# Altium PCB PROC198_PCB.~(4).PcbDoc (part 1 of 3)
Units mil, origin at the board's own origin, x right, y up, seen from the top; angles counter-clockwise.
Board outline 858.22 x 1632.74 mil, 4 copper layers (Top Layer, L2_GND1, L3_PWR1, Bottom Layer), stack 54.546 mil thick; 116 components, 64 nets, 355 pads, 1018 vias.
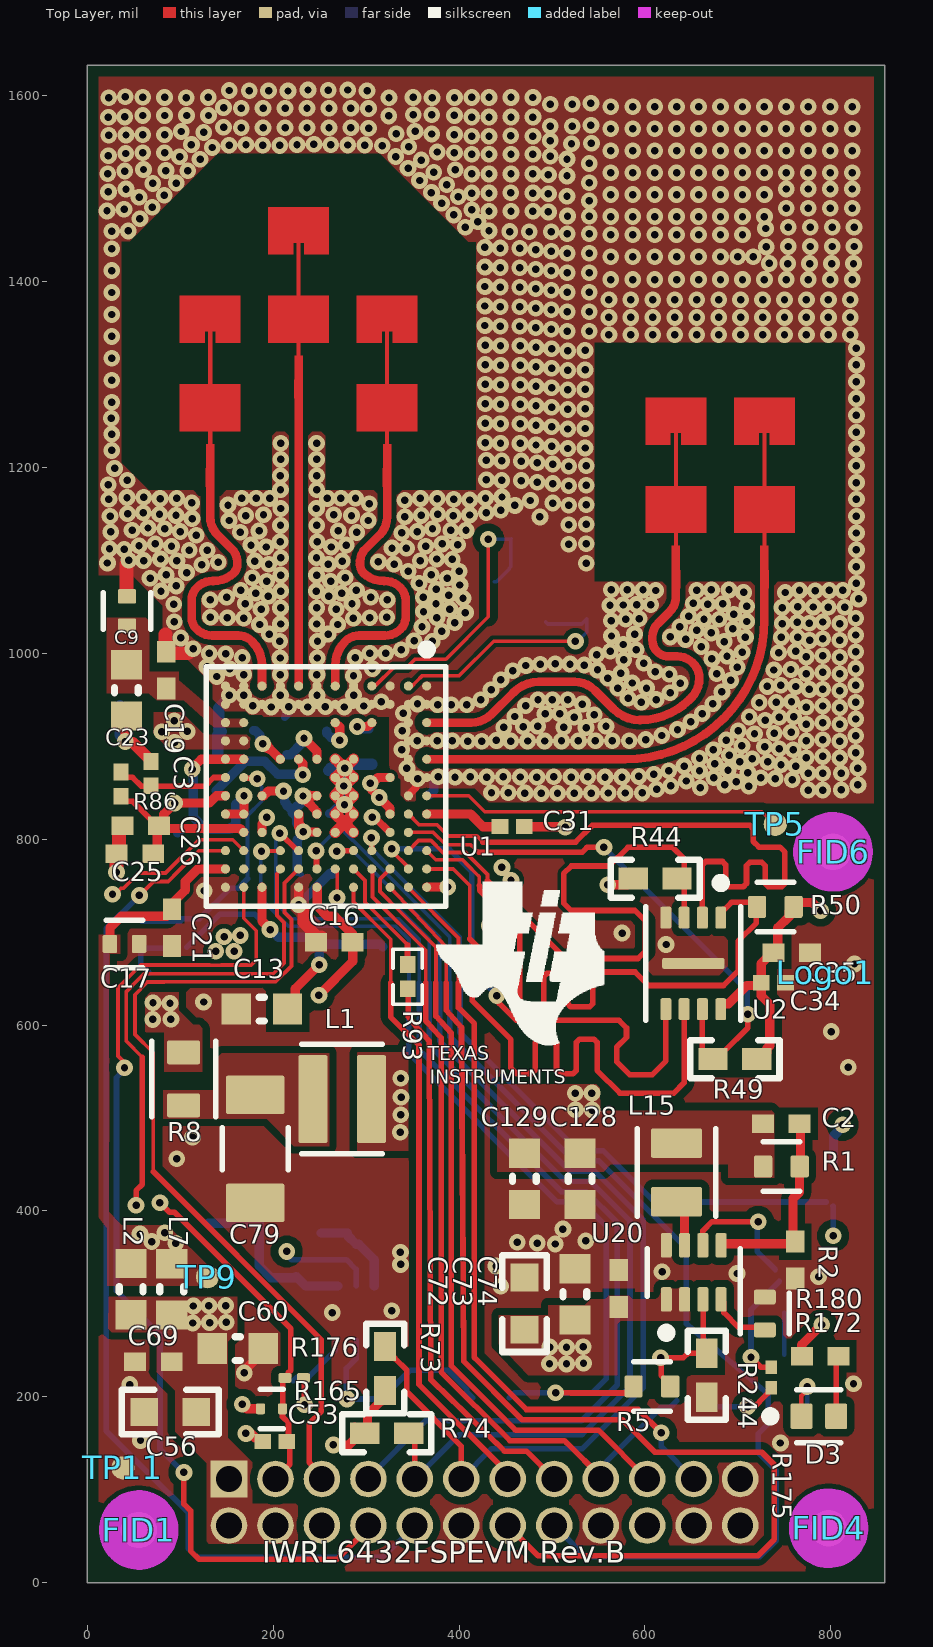
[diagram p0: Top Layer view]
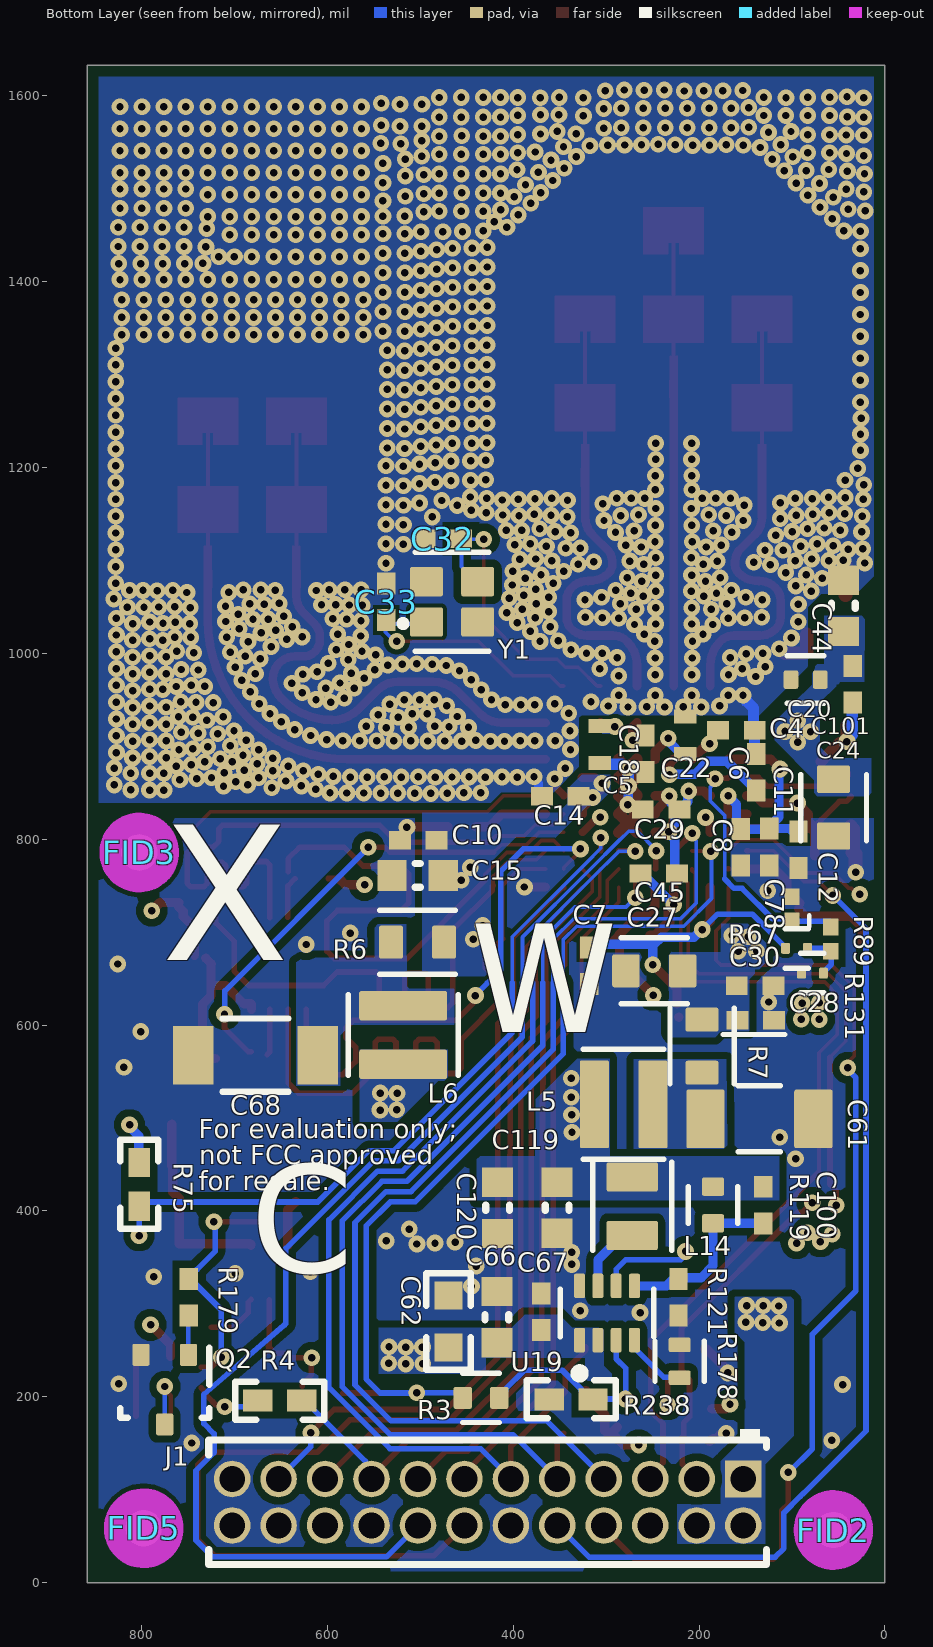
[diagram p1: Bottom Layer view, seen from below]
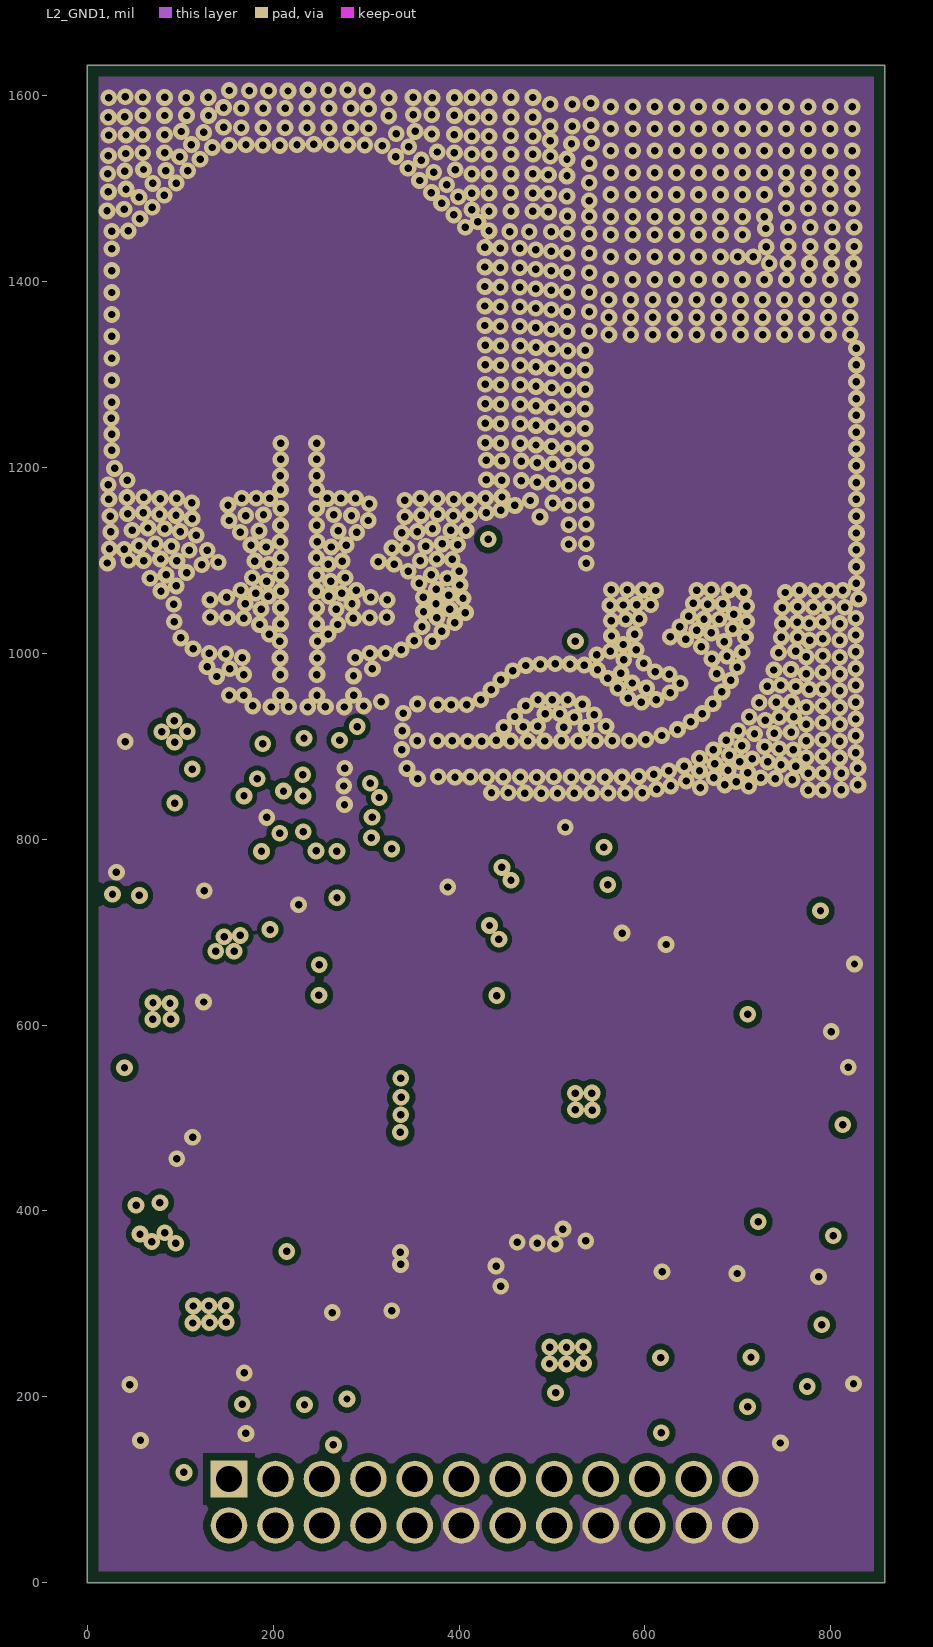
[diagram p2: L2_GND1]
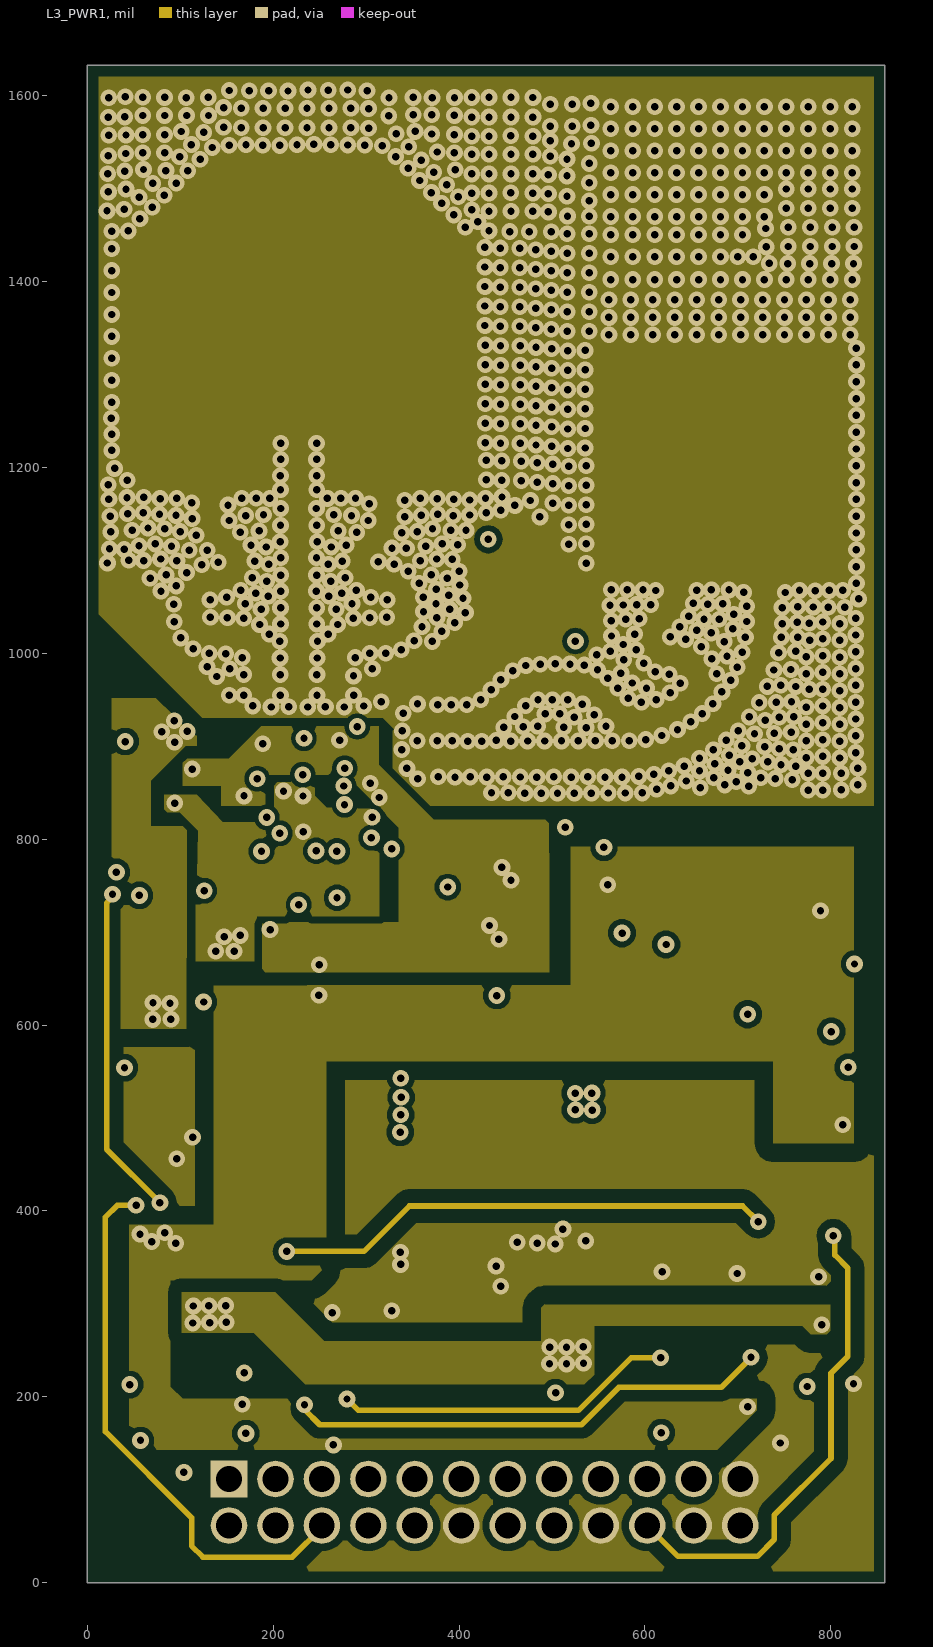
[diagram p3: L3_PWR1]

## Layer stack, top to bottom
Top Solder: solder mask 0.8, Solder Resist, Dk 3.2
Top Layer: signal copper 1.378
Dielectric 1: core 5, Isola FR408HR (DUAL PLY, 2x1067, SPREAD GLASS ), Dk 3.3
L2_GND1: signal copper 1.2
Dielectric 4: core 39.39, Isola FR408HR (DUAL PLY, 2x1067, SPREAD GLASS ), Dk 4.28
L3_PWR1: signal copper 1.2
Dielectric 3: prepreg 5, Isola FR408HR (DUAL PLY, 2x1067, SPREAD GLASS ), Dk 3.79
Bottom Layer: signal copper 1.378
Bottom Solder: solder mask 0.8, Solder Resist, Dk 3.2

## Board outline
0,0 0,1632.75 858.22,1632.75 858.22,0

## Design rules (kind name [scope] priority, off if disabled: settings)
AcuteAngle [All] p1 off: minimum=4.50000000000000E+0001 checktracksonly=FALSE
AssemblyTestPointUsage [All] p1: valid=2
BoardOutlineClearance [All] p1: gap=12 ignorepadtopadclearanceinfootprint=FALSE
Clearance Clearance_Keepout [IsKeepOut] p1: gap=5 ignorepadtopadclearanceinfootprint=TRUE
Clearance "Clearance_TX and RX" [InNetClass('TX and RX')] p2: gap=8 ignorepadtopadclearanceinfootprint=FALSE except(0: Text-Hole; 4: Arc-Text Track-Text SMDPad-Text THPad-Text Via-Text Fill-Text Poly-Text Region-Text Text-Text; 5.3: Arc-Via Arc-Fill Arc-Poly Arc-Region Track-Via Track-Fill Track-Poly Track-Region Poly-Region; 6: Arc-Hole Track-Hole SMDPad-Via SMDPad-Hole THPad-Hole Via-Hole; 7.7: Fill-Fill Fill-Poly Fill-Region Poly-Poly Region-Region; 10: Arc-SMDPad Arc-THPad Track-SMDPad Track-THPad SMDPad-SMDPad SMDPad-THPad THPad-THPad THPad-Via; 11: Fill-Hole Poly-Hole Region-Hole)
Clearance Clearance_BGA [WithinRoom('BGA1')] p3: gap=4 ignorepadtopadclearanceinfootprint=FALSE except(8: Fill-Fill Fill-Poly Fill-Region Poly-Poly Poly-Region Region-Region; 10: Fill-Hole Poly-Hole Region-Hole)
Clearance "top and bottom" [OnTopLayer or OnBottomLayer] p4: gap=6 ignorepadtopadclearanceinfootprint=TRUE except(5: Arc-Arc Arc-Track Arc-SMDPad Arc-Hole Track-Track Track-SMDPad Track-Hole SMDPad-Hole THPad-Hole Via-Hole Text-Hole; 5.1: SMDPad-SMDPad; 7: Arc-Fill Arc-Poly Arc-Region Track-Fill Track-Region; 8: Track-Poly SMDPad-Fill SMDPad-Poly SMDPad-Region THPad-Fill THPad-Poly THPad-Region Via-Fill Via-Poly Via-Region Poly-Poly; 10: Fill-Fill Fill-Poly Fill-Region Poly-Region Region-Region; 11: Fill-Hole Poly-Hole Region-Hole)
Clearance Clearance_KO-J5 [IsKeepOut and IsTrack vs InComponent('J5')] p5: gap=19.6 ignorepadtopadclearanceinfootprint=FALSE
Clearance "Inner layers" [OnLayer('L3_PWR1') vs InNet('GND')] p6: gap=6 ignorepadtopadclearanceinfootprint=TRUE except(0: Text-Hole; 5: Arc-Arc Arc-Track Arc-SMDPad Track-Track Track-SMDPad; 5.1: SMDPad-SMDPad; 7: Arc-Fill Arc-Poly Arc-Region Track-Fill Track-Region; 8: SMDPad-Fill SMDPad-Poly SMDPad-Region THPad-Fill THPad-Poly THPad-Region; 10: Fill-Fill Fill-Poly Fill-Region Poly-Region Region-Region; 11: Fill-Hole Poly-Hole Region-Hole; 15: Track-Poly; 20: Poly-Poly)
Clearance [All] p7: gap=6 ignorepadtopadclearanceinfootprint=TRUE except(0: Text-Hole; 5: Arc-Arc Arc-Track Arc-SMDPad Track-Track Track-SMDPad; 5.1: SMDPad-SMDPad; 7: Arc-Fill Arc-Poly Arc-Region Track-Fill Track-Region; 8: SMDPad-Fill SMDPad-Poly SMDPad-Region THPad-Fill THPad-Poly THPad-Region; 10: Fill-Fill Fill-Poly Fill-Region Poly-Region Region-Region; 11: Fill-Hole Poly-Hole Region-Hole; 12: Track-Poly; 15: Poly-Poly)
Clearance Same_net [All] p8: gap=0 ignorepadtopadclearanceinfootprint=TRUE
ComponentClearance ComponentClearance_MatingCon-3D [All vs not InAnyComponent] p1: gap=0 collisioncheckmode=3 verticalgap=0 showdistances=FALSE
ComponentClearance "ComponentClearance_WEE Logo" [InComponent('Logo4')] p2: gap=0 collisioncheckmode=3 verticalgap=0 showdistances=TRUE
ComponentClearance ComponentClearance_R77 [InComponent('R77') vs InComponent('Logo1')] p3: gap=0 collisioncheckmode=3 verticalgap=0 showdistances=TRUE
ComponentClearance ComponentClearance_Logo [InComponentClass('Logo')] p4: gap=0 collisioncheckmode=3 verticalgap=0 showdistances=TRUE
ComponentClearance "ComponentClearance_Mounting Holes_Fiducial Marks" [InComponentClass('FiducialMark') vs InPadClass('Mounting Holes PADS')] p5: gap=50 collisioncheckmode=3 verticalgap=10 showdistances=TRUE
ComponentClearance [All] p6: gap=6 collisioncheckmode=3 verticalgap=10 showdistances=TRUE
DiffPairsRouting [All] p1: maxlimit=10 minlimit=10 mostfreqgap=10 toplayer_minwidth=15 toplayer_maxwidth=15 toplayer_prefwidth=15 midlayer1_minwidth=15 midlayer1_maxwidth=15 midlayer1_prefwidth=15 midlayer5_minwidth=15 midlayer5_maxwidth=15 midlayer5_prefwidth=15 bottomlayer_minwidth=15 bottomlayer_maxwidth=15 bottomlayer_prefwidth=15 maxuncoupledlength=500
FabricationTestPointUsage TestPointUsage [All] p1: valid=2 allowmultiple=FALSE
FabricationTestpoint Testpoint [All] p1: side=3 testpointundercomponent=TRUE minsize=40 maxsize=100 preferedsize=60 minholesize=0 maxholesize=40 preferedholesize=32 testpointgrid=1 allowsidetop=TRUE allowsidebottom=TRUE usegrid=TRUE gridtolerance=0.01
FanoutControl Fanout_LCC [IsLCC] p1: bgadir=Out bgaviamode=Centered fanoutstyle=Auto fanoutdirection=Alternating viagrid=1 // Fanout_LCC (Default Rule)
FanoutControl Fanout_BGA [IsBGA] p2: bgadir=Out bgaviamode=Centered fanoutstyle=Auto fanoutdirection=Alternating viagrid=1 // Fanout_BGA (Default Rule)
FanoutControl Fanout_Default [All] p4: bgadir=Out bgaviamode=Centered fanoutstyle=Auto fanoutdirection=Alternating viagrid=1 // Fanout_Default (Default Rule)
FanoutControl Fanout_Small [(CompPinCount < 5)] p5: bgadir=Out bgaviamode=Centered fanoutstyle=Auto fanoutdirection=OutThenIn viagrid=1 // Fanout_Small (Default Rule)
Height Room_Hieght [WithinRoom('Room_Hieght 1 MM')] p1: minheight=0 maxheight=41.34 prefheight=39.37
HoleSize [All] p1: absolutevalues=TRUE maxlimit=280 minlimit=5.9 maxpercent=80.000 minpercent=20.000
HoleToHoleClearance HoleToHoleClearance_1 [WithinRoom('BGA1')] p1: gap=4 allowstackedmicrovias=FALSE
MatchedLengths MatchLengths_xSignals_U2_U1_1 [InxSignalClass('xSignals_U2_U1_MatchLengthsClass_1')] p1: tolerance=100 checknetsindiffpair=FALSE checkdiffpairvsdiffpair=TRUE checkxsignals=TRUE checkothers=TRUE
MatchedLengths MatchLengths_U2_Passives_U1 [InxSignalClass('xSignals_U2_Passives_U1_MatchLengthsClass')] p2: tolerance=100 checknetsindiffpair=FALSE checkdiffpairvsdiffpair=TRUE checkxsignals=TRUE checkothers=TRUE
MatchedLengths MatchLengths_xSignals_U2_Passives [InxSignalClass('xSignals_U2_Passives_MatchLengthsClass')] p3: tolerance=100 checknetsindiffpair=FALSE checkdiffpairvsdiffpair=TRUE checkxsignals=TRUE checkothers=TRUE
MatchedLengths MatchLengths_xSignals_U2_U1 [InxSignalClass('xSignals_U2_U1_MatchLengthsClass')] p4: tolerance=100 checknetsindiffpair=FALSE checkdiffpairvsdiffpair=TRUE checkxsignals=TRUE checkothers=TRUE
MatchedLengths [InxSignalClass('QPSI')] p5: tolerance=10 checknetsindiffpair=FALSE checkdiffpairvsdiffpair=TRUE checkxsignals=TRUE checkothers=TRUE
MinimumAnnularRing MinimumAnnularRing_ThermalPadVias [IsVia and InAnyComponent] p1: minimumring=3.9
MinimumAnnularRing [All] p2: minimumring=3.9
MinimumSolderMaskSliver MinimumSolderMaskSliver_Logo [InComponentClass('Logo') vs InComponentClass('Logo')] p1: minsoldermaskwidth=0.7
MinimumSolderMaskSliver [All] p2: minsoldermaskwidth=3.5
PlaneConnect [All] p1: planeconnectstyle=Relief reliefexpansion=10 reliefentries=4 reliefconductorwidth=10 reliefairgap=10
PolygonConnect [All] p1: connectstyle=Direct reliefconductorwidth=10 reliefentries=4 polygonreliefangle="90 Angle" airgapwidth=10
RoomDefinition BGA1 [InComponentClass('Components Class 2')] p1: confinementstyle=ConfineIn formatcopy=TRUE lockcomponents=FALSE outline 82.66,1059.13 551.45,1059.13 551.45,645.43 82.66,645.43
RoutingVias ThermalPadVias [IsVia and InAnyComponent] p1: holewidth=7.87 width=19.68 viastyle="Through Hole" minholewidth=5 minwidth=13 maxholewidth=12.99 maxwidth=23.62
RoutingVias [All] p2: holewidth=12.2 width=22.4 viastyle="Through Hole" minholewidth=5.9 minwidth=14 maxholewidth=20 maxwidth=40
SMDToCorner [All] p1: distance=25000
SilkToBoardRegionClearance [Not ((IsComment or IsDesignator) And (Hide <> 'False')) and not InRegion(1000,500,4000,800)] p1:
SilkToSilkClearance [All] p1: silktosilkclearance=3
SilkToSolderMaskClearance SilkToSolderMaskClearance_OutLine [istrack and InAnyComponent] p1: minsilkscreentomaskgap=0 clearancetoexposedcopper=FALSE
SilkToSolderMaskClearance SilkscreenOverComponentPads [IsPad] p2: minsilkscreentomaskgap=3 clearancetoexposedcopper=FALSE
SolderMaskExpansion [All] p1: expansion=0 istentingtop=FALSE
SupplyNets "Schematic Supply Nets_15" [InNet('RADAR_1V_RF_OUT')] p1: voltage=0.000
SupplyNets "Schematic Supply Nets_14" [InNet('REG_RF_1V2')] p2: voltage=0.000
SupplyNets "Schematic Supply Nets_13" [InNet('RADAR_1P2_RF')] p3: voltage=0.000
SupplyNets "Schematic Supply Nets_12" [InNet('REG_OUT_1V8')] p4: voltage=0.000
SupplyNets "Schematic Supply Nets_11" [InNet('REG_1V2')] p5: voltage=0.000
SupplyNets "Schematic Supply Nets_10" [InNet('RADAR_1V4_APLL')] p6: voltage=0.000
SupplyNets "Schematic Supply Nets_9" [InNet('GND')] p7: voltage=0.000
SupplyNets "Schematic Supply Nets_8" [InNet('RADAR_1V2')] p8: voltage=0.000
SupplyNets "Schematic Supply Nets_7" [InNet('RADAR_1V4_SYNTH')] p9: voltage=0.000
SupplyNets "Schematic Supply Nets_6" [InNet('RADAR_3V3')] p10: voltage=0.000
SupplyNets "Schematic Supply Nets_5" [InNet('REG_OUT_1V2')] p11: voltage=0.000
SupplyNets "Schematic Supply Nets_4" [InNet('RADAR_1V8')] p12: voltage=0.000
SupplyNets "Schematic Supply Nets_3" [InNet('REG_1V8')] p13: voltage=0.000
SupplyNets "Schematic Supply Nets_2" [InNet('VPP_1P7')] p14: voltage=0.000
SupplyNets "Schematic Supply Nets_1" [InNet('RADAR_VBGAP')] p15: voltage=0.000
SupplyNets "Schematic Supply Nets" [InNet('INPUT_3V3')] p16: voltage=0.000
UnRoutedNet [All] p1: checkbadconnections=TRUE
Width [All] p1: maxlimit=100 minlimit=4 preferedwidth=10 toplayer_prefwidth=6 midlayer1_minwidth=6 midlayer5_minwidth=6 minimp=50.000000 maximp=50.000000 favimp=50.000000
12 further rules are at their usual default settings.

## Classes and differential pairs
net class LVDS_D: LVDS_D0_LIN_PHY_RX LVDS_D1_XDS_UARTA_RX_CAN_RX LVDS_D2_XDS_UARTA_TX_CAN_TX LVDS_FRCLK_HOST_CLK_TP
net class POWER: INPUT_3V3 PMIC_CLKOUT_LIN_PHY_TX_SOP1 REG_1V2 REG_1V8 REG_OUT_1V2 REG_OUT_1V8 REG_PG REG_RF_1V2
component class PROC198_DC_Regulators: C2 C56 C60 C61 C62 C66 C67 C68 C69 C72 C73 C74 C79 C100 C119 C120 C128 C129 D3 L1 L5 L6 L14 L15 Q2 R1 R2 R3 R5 R119 R121 R172 R175 R176 R178 R179 R180 R238 R244 TP9 TP11 U19 U20
net class Regions: GND INPUT_3V3 XTALP
component class Logo: Logo1
component class FiducialMark: FID1 FID2 FID3 FID4 FID5 FID6
component class PROC198_Decoupling_caps: C4 C5 C6 C7 C8 C9 C10 C11 C12 C13 C14 C15 C16 C17 C18 C19 C20 C21 C22 C23 C24 C25 C26 C27 C28 C29 C30 C44 C45 C101 L2 L7 R6 R7 R8
component class PROC198_Hardware: FID1 FID2 FID3 FID4 FID5 FID6 Logo1 ZZ1 ZZ2 ZZ3 ZZ4 ZZ5
component class PROC198_xWRL6432_Chip: C3 C31 C32 C33 C53 C78 R4 R67 R73 R74 R75 R86 R89 R93 R131 R165 TP5 U1 Y1
component class PROC198_QSPI_Flash: C34 C35 R44 R49 R50 U2
net class "TX and RX": RX1 RX2 RX3 TX1 TX2
component class AssemblyNote: ZZ1 ZZ2 ZZ3 ZZ4 ZZ5
component class PROC198_PWR_Connector: FL1 FL2 J1 LD1
component class Header: J1 LD2 LD4 SW1 SW2
differential pair CAN: +"" -""
differential pair LVDS_FRCLK: +"" -""
differential pair LVDS_FRCLK_DP8: +"" -""
differential pair LVDS_CLK: +"" -""
differential pair LVDS_CLK_DP7: +"" -""
differential pair LVDS_3: +"" -""
differential pair LVDS_3_DP6: +"" -""
differential pair LVDS_2: +"" -""
differential pair LVDS_2_DP5: +"" -""
differential pair LVDS_1: +"" -""
differential pair LVDS_1_DP4: +"" -""
differential pair LVDS_0: +"" -""
differential pair LVDS_0_DP3: +"" -""
differential pair USB_DP1: +"" -""

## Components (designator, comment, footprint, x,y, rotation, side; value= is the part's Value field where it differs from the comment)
C2 "GRM1555C1H100JA01D" 0402L 746.86,493.69 r0 top value=10pF
C3 "GRM033R60J105MEA2D" 0201_033 68.47,870.55 r90 top value=1uF
C4 "GRM155R71C224KA12D" 0402L 159.72,917.18 r180 bottom value=0.22uF
C5 "GRM155R71C224KA12D" 0402L 257.59,891.86 r270 bottom value=0.22uF
C6 "C1005X7R1H473K050BB" 0402L 138.57,872.17 r90 bottom value=0.047uF
C7 "GRM155R71C224KA12D" 0402L 318.14,663.94 r270 bottom value=0.22uF
C8 "GRM155R71C224KA12D" 0402L 155.05,791.52 r270 bottom value=0.22uF
C9 "GRM155R61A225ME01D" FP-GRM155R61A225ME01D_0402-MFG 42.69,1045.59 r270 top value=2.2¦ÌF
C10 "GRM155R71C224KA12D" 0402L 502.27,798.91 r0 bottom value=0.22uF
C11 "GRM155R71C224KA12D" 0402L 124.42,791.63 r270 bottom value=0.22uF
C12 "GRM155R71C224KA12D" 0402L 92.89,788.72 r270 bottom value=0.22uF
C13 "GRM188Z71A106MA73D" 0603L 187.91,617.22 r180 top value=10uF
C14 "GRM155R71C224KA12D" 0402L 349.34,846.17 r0 bottom value=0.22uF
C15 "GRM188Z71A106MA73D" 0603L 502.78,761.04 r0 bottom value=10uF
C16 "GRM155R71C224KA12D" 0402L 265.87,689.23 r180 top value=0.22uF
C17 "GRM155R61A225ME01D" FP-GRM155R61A225ME01D_0402-MFG 40.03,687.29 r180 top value=2.2¦ÌF
C18 "GRM155R70J105KA12D" 0402S 306.74,901.81 r270 bottom value=1uF
C19 "GRM155R71C224KA12D" 0402L 84.89,982.05 r90 top value=0.22uF
C20 "GRM155R61A225ME01D" FP-GRM155R61A225ME01D_0402-MFG 85.33,971.74 r180 bottom value=2.2¦ÌF
C21 "GRM155R71C224KA12D" 0402L 91.21,704.94 r270 top value=0.22uF
C22 "GRM155R70J105KA12D" 0402S 214.93,911.89 r90 bottom value=1uF
C23 "GRM188Z71A106MA73D" 0603L 42,960.25 r270 top value=10uF
C24 "GRM188C71C475KE21D" FP-GRM188C71C475KE21D_0603-MFG 55.22,833.97 r90 bottom value=4.7¦ÌF
C25 "GRM155R71C224KA12D" 0402L 51.23,784.28 r180 top value=0.22uF
C26 "GRM155R71C224KA12D" 0402L 57.34,814.62 r180 top value=0.22uF
C27 "GRM188C71C475KE21D" FP-GRM188C71C475KE21D_0603-MFG 248.11,658.39 r180 bottom value=4.7¦ÌF
C28 "GRM155R71C224KA12D" 0402L 138.85,605.27 r180 bottom value=0.22uF
C29 "GRM155R71C224KA12D" 0402L 240.86,832.03 r0 bottom value=0.22uF
C30 "GRM155R71E103KA01D" 0402L 139.73,642.48 r180 bottom value=0.01uF
C31 "GRM033C71A104KE14D" 0201 457.18,813.7 r180 top value=0.1uF
C32 "GJM1555C1H4R7BB01D" 0402L 475.81,1123.2 r180 bottom value=4.7pF
C33 "GJM1555C1H4R7BB01D" 0402L 536.48,1055.64 r270 bottom value=4.7pF
C34 "GRM033C71A104KE14D" 0201 738.14,645.51 r180 top value=0.1uF
C35 "GRM155R70J105KA12D" 0402L 758.09,677.68 r0 top value=1uF
C44 "GRM188Z71A106MA73D" 0603L 44.64,1051.13 r90 bottom value=10uF
C45 "GRM155R71E103KA01D" 0402L 243.26,763.06 r0 bottom value=0.01uF
C53 "GRM033C71A104KE14D" 0201 201.67,151.96 r0 top value=0.1uF
C56 "GRM188Z71A106MA73D" 0603_HV 89.23,183.79 r180 top value=10uF
C60 "GRM188R71C474KA88D" 0603L 161.83,251.85 r0 top value=0.47uF
C61 "GRM31CR70J226ME19K" FP-GRM31CR70J226ME19K_1206-MFG 134.98,499.04 r0 bottom value=22¦ÌF
C62 "GRM188Z71A106MA73D" 0603_HV 469.53,281.09 r90 bottom value=10uF
C66 "GRM188R71C474KA88D" 0603L 417.45,285.83 r90 bottom value=0.47uF
C67 "GRM1555C1H471JA01D" 0402L 369.91,291.71 r90 bottom value=470pF
C68 "GRM31CR60J476ME19L" 1206_180 677.32,567.57 r180 bottom value=47uF
C69 "GRM1555C1H471JA01D" 0402L 71.14,237.77 r180 top value=470pF
C72 "GRM188Z71A106MA73D" 0603_HV 470.33,300.21 r90 top value=10uF
C73 "GRM188R71C474KA88D" 0603L 524.56,310.1 r90 top value=0.47uF
C74 "GRM1555C1H471JA01D" 0402L 571.9,316.52 r90 top value=470pF
C78 "GRM033R60J105MEA2D" 0201_033 100.01,725.16 r90 bottom value=1uF
C79 "GRM31CR70J226ME19K" FP-GRM31CR70J226ME19K_1206-MFG 180.55,466.8 r90 top value=22¦ÌF
C100 "GRM1555C1H100JA01D" 0402L 130.75,406.36 r270 bottom value=10pF
C101 "GRM155R71C224KA12D" 0402L 34.66,966.8 r270 bottom value=0.22uF
C119 "GRM188Z71A106MA73D" 0603L 352.73,403.42 r270 bottom value=10uF
C120 "GRM188Z71A106MA73D" 0603L 416.69,403.3 r270 bottom value=10uF
C128 "GRM188Z71A106MA73D" 0603L 530.24,434.46 r270 top value=10uF
C129 "GRM188Z71A106MA73D" 0603L 470.33,434.46 r270 top value=10uF
D3 "VLMY1500-GS08" FP-VLMY1500-GS08_0402-MFG 787.14,179 r0 top
FID1 "Fiducial" Fiducial10-20 55.34,56.66 r0 top
FID2 "Fiducial" Fiducial10-20 55.34,56.66 r90 bottom
FID3 "Fiducial" Fiducial10-20 802.39,785.73 r90 bottom
FID4 "Fiducial" Fiducial10-20 797.69,58.55 r0 top
FID5 "Fiducial" Fiducial10-20 797.69,58.55 r90 bottom
FID6 "Fiducial" Fiducial10-20 802.39,786.41 r0 top
J1 "GRPB122VWVN-RC" Sullins_GRPB122VWVN 427.43,86.54 r270 bottom locked
L1 "LQM2MPZR10MJHL" "FP-LQM2MPZR10MJHL_0806 (2016)-MFG" 274.26,520.38 r180 top value=0.1uH
L2 "BLM18KG121TH1D" 0603L 47.18,315.97 r90 top value="120 ohm"
L5 "LQM2MPZR10MJHL" "FP-LQM2MPZR10MJHL_0806 (2016)-MFG" 281.1,514.75 r180 bottom value=0.1uH
L6 "LQM2MPZR10MJHL" "FP-LQM2MPZR10MJHL_0806 (2016)-MFG" 518.41,589.33 r90 bottom value=0.1uH
L7 "BLM18KG121TH1D" 0603L 90.83,315.66 r90 top value="120 ohm"
L14 "DFE201210U-R47M=P2" "FP-DFE201210U-R47M=P2_0805 (2012)-MFG" 271.83,405.14 r90 bottom value=0.47uH
L15 "DFE201210U-R47M=P2" "FP-DFE201210U-R47M=P2_0805 (2012)-MFG" 634.01,441.4 r90 top value=0.47uH
Logo1 "Texas Instruments" TI_Stacked_Overlay_Small 793.8,656.14 r0 top
Q2 "BSS123W-7-F" SOT-323 774.97,207.75 r270 bottom value=100V
R1 "RC0402JR-070RP" FP-RC0402JR-070RP_0402-MFG 746.86,447.83 r180 top value=0
R2 "CRCW040240K2FKED" 0402L 761.71,347.19 r90 top value=40.2k
R3 "RC0402JR-070RP" FP-RC0402JR-070RP_0402-MFG 434.62,198.92 r0 bottom value=0
R4 "CRCW04022M00FKED" 0402 651.26,195.93 r180 bottom value=2.00Meg
R5 "RC0402JR-070RP" FP-RC0402JR-070RP_0402-MFG 607.48,211.2 r180 top value=0
R6 "ERJ-3GEY0R00V" FP-ERJ-3GEY0R00V_0603-MFG 502.94,689.23 r180 bottom
R7 "ERJ-3GEY0R00V" FP-ERJ-3GEY0R00V_0603-MFG 196.78,577.37 r90 bottom
R8 "ERJ-3GEY0R00V" FP-ERJ-3GEY0R00V_0603-MFG 103.52,542.07 r90 top
R44 "CRCW04022M00FKED" 0402 610.99,757.67 r180 top value=2.00Meg
R49 "CRCW04022M00FKED" 0402 696.82,563.35 r0 top value=2.00Meg
R50 "AC0402FR-0747K5L" FP-AC0402FR-0747K5L_0402-MFG 740.31,727.13 r180 top value=47.5k
R67 "ERJ-1RHD1002C" FP-ERJ-1RHD1002C_0201-MFG 95.09,682.57 r0 bottom value=10k
R73 "CRCW04022M00FKED" 0402 320.39,230.42 r90 top value=2.00Meg
R74 "CRCW04022M00FKED" 0402 322.19,160.76 r0 top value=2.00Meg
R75 "CRCW04022M00FKED" 0402 802.39,428.61 r270 bottom value=2.00Meg
R86 "CRCW02011K00FKED" 0201 36.21,859.22 r90 top value=1.00k
R89 "CRCW02011K00FKED" 0201 58.33,692.47 r90 bottom value=1.00k
R93 "CRCW020133R2FNED" 0201_Silk 344.67,652.08 r90 top value=33.2
R119 "RC0402JR-070RP" FP-RC0402JR-070RP_0402-MFG 184.93,406.36 r90 bottom value=0
R121 "RC0402FR-0768K1L" 0402L 222,307.29 r90 bottom value=68.1k
R131 "ERJ-1RHD1002C" FP-ERJ-1RHD1002C_0201-MFG 77.98,655.89 r180 bottom value=10k
R165 "ERJ-1RHD1002C" FP-ERJ-1RHD1002C_0201-MFG 198.23,187.09 r180 top value=10k
R172 "ERJ-2RKF5100X" 0402L 788.67,243.59 r0 top value=510
R175 "CRCW0201100KFKED" 0201L 735.87,220.73 r90 top value=100k
R176 "RC0201JR-070RL" "FP-RC0201JR-070RL_0201 (0603 Metric)-IPC_C" 222.5,220.26 r0 top
R178 "CRCW040218K0FKEDC" FP-CRCW040218K0FKEDC_0402-MFG 220.81,238.11 r90 bottom value=18k
R179 "ERJ-2RKF5100X" 0402L 749.25,307.29 r90 bottom value=510
R180 "CRCW040218K0FKEDC" FP-CRCW040218K0FKEDC_0402-MFG 728.97,289.66 r90 top value=18k
R238 "RC0402FR-071ML" 0402 337.63,197.23 r180 bottom value=1.00Meg
R244 "RC0402FR-071ML" 0402 666.52,223.23 r90 top value=1.00Meg
TP5 "TESTPOINT" TP_25MIL-SMT 740.31,816.1 r90 top
TP9 "TESTPOINT" TP_25MIL-SMT 129.29,329.23 r0 top
TP11 "TESTPOINT" TP_25MIL-SMT 38.36,123.51 r90 top
U1 "IWRL6432QGAMF" AMF0102A-MFG 256.89,856.58 r270 top locked
U2 "W25Q16JVUXIQ" FP-W25Q16JVUXIQ_USON8-MFG 652.06,666.32 r270 top
U19 "TPS6285020ADRLR" DRL0008A-MFG 299,290.16 r90 bottom
U20 "TPS6285020MDRLR" DRL0008A-MFG 652.49,333.86 r90 top
Y1 "FW4000044Q" FP-FW4000044Q_4-SMD-2.0x1.6mm-MFG 465.78,1055.41 r180 bottom
ZZ1 "This Assembly Note is for PCB labels only" AssemblyNoteLabel -1677.83,2575.17 r0 top
ZZ2 "These assemblies are ESD sensitive, ESD precautions shall be observed." AssemblyNote -1675.42,2497.19 r0 top
ZZ3 "These assemblies must be clean and free from flux and all contaminants. Use of no clean flux is not acceptable." AssemblyNote -1675.42,2410.38 r0 top
ZZ4 "These assemblies must comply with workmanship standards IPC-A-610 Class 2, unless otherwise specified." AssemblyNote -1654.85,2341.65 r0 top
ZZ5 "These assemblies must comply with workmanship standards IPC-A-610 Class 2, unless otherwise specified." AssemblyNote -1653.46,2254.06 r0 top

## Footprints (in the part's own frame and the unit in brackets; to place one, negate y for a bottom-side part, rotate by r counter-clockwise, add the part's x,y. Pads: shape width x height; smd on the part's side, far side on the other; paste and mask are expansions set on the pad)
0201 [mm] "Data from Kemet datasheet CC101_COM dated 7/28/11"
  rect 0.46x0.42 smd mask+0.048: 1(-0.33,0) 2(0.33,0)
  body extent -0.31,-0.16 0.31,0.16, height 0.26
0201_033 [mm] "SMD, 2-Leads, Height 0.33mm"
  rect 0.46x0.42 smd mask+0.048: 1(-0.33,0) 2(0.33,0)
  body extent -0.31,-0.16 0.31,0.16, height 0.33
0201_Silk [mm] "Data from Kemet datasheet CC101_COM dated 7/28/11"
  rect 0.46x0.42 smd mask+0.048: 1(-0.33,0) 2(0.33,0)
  silkscreen extent -0.75,-0.4 0.75,0.4, body extent -0.31,-0.16 0.31,0.16, height 0.26
0201L [mm] "Data from Kemet datasheet CC101_COM dated 7/28/11"
  rect 0.36x0.32 smd mask+0.048: 1(-0.28,0) 2(0.28,0)
  body extent -0.31,-0.16 0.31,0.16, height 0.26
0402 [mm] "0402 from SM-752 data"
  rect 0.8x0.6 smd: 1(-0.6,0) 2(0.6,0)
  silkscreen extent -1.22,-0.52 1.22,0.52, body extent -0.55,-0.3 0.55,0.3, height 0.6
0402L [mm] "0402 from SM-752 data"
  rect 0.6x0.5 smd: 1(-0.5,0) 2(0.5,0)
  body extent -0.55,-0.3 0.55,0.3, height 0.6
0402S [mil] "Based on C0402S footprint from PADS legacy"
  rect 15x24 smd: 1(-20,0) 2(20,0)
  body extent -22,-12 22,12, height 24
0603_HV [mil] "Ernesto recommended land pattern.  26 mil between pads."
  rect 30x30 smd: 1(-28,0) 2(28,0)
  silkscreen extent -52,-24 52,24, body extent -34,-19 34,19, height 39
0603L [mm] "0603 from SM-752 data"
  rect 0.8x0.85 smd: 1(-0.7,0) 2(0.7,0)
  silkscreen extent -0.07,-0.33 0.07,0.33, body extent -0.87,-0.47 0.87,0.47, height 1
1206_180 [mm] "1206_180"
  rect 1.1x1.6 smd: 1(-1.7,0) 2(1.7,0)
  silkscreen extent -0.9,-1 0.9,1, body extent -1.75,-0.95 1.75,0.95, height 1.8
AMF0102A-MFG [mm]
  round 0.25 smd paste+0 mask-1000: A1(-2.75,2.75) A2(-2.25,2.75) A3(-1.75,2.75) A4(-1.25,2.75) A5(-0.75,2.75) A6(-0.25,2.75) A7(0.25,2.75) A8(0.75,2.75) A10(1.75,2.75) A11(2.25,2.75) A12(2.75,2.75) B1(-2.75,2.25) B2(-2.25,2.25) B3(-1.75,2.25) B4(-1.25,2.25) B5(-0.75,2.25) B6(-0.25,2.25) B7(0.25,2.25) B8(0.75,2.25) B9(1.25,2.25) B10(1.75,2.25) B11(2.25,2.25) B12(2.75,2.25) C1(-2.75,1.75) C2(-2.25,1.75) C6(-0.25,1.75) C8(0.75,1.75) C9(1.25,1.75) C11(2.25,1.75) C12(2.75,1.75) D1(-2.75,1.25) D2(-2.25,1.25) D3(-1.75,1.25) D10(1.75,1.25) D11(2.25,1.25) E1(-2.75,0.75) E2(-2.25,0.75) E5(-0.75,0.75) E6(-0.25,0.75) E7(0.25,0.75) E8(0.75,0.75) E9(1.25,0.75) E10(1.75,0.75) E11(2.25,0.75) E12(2.75,0.75) F1(-2.75,0.25) F2(-2.25,0.25) F3(-1.75,0.25) F5(-0.75,0.25) F6(-0.25,0.25) F7(0.25,0.25) F8(0.75,0.25) F9(1.25,0.25) F11(2.25,0.25) G1(-2.75,-0.25) G2(-2.25,-0.25) G5(-0.75,-0.25) G7(0.25,-0.25) G8(0.75,-0.25) G9(1.25,-0.25) G11(2.25,-0.25) G12(2.75,-0.25) H1(-2.75,-0.75) H2(-2.25,-0.75) H5(-0.75,-0.75) H8(0.75,-0.75) H10(1.75,-0.75) H11(2.25,-0.75) H12(2.75,-0.75) J1(-2.75,-1.25) J2(-2.25,-1.25) J5(-0.75,-1.25) J10(1.75,-1.25) J11(2.25,-1.25) K1(-2.75,-1.75) K2(-2.25,-1.75) K7(0.25,-1.75) K9(1.25,-1.75) K11(2.25,-1.75) K12(2.75,-1.75) L1(-2.75,-2.25) L2(-2.25,-2.25) L3(-1.75,-2.25) L4(-1.25,-2.25) L5(-0.75,-2.25) L6(-0.25,-2.25) L8(0.75,-2.25) L9(1.25,-2.25) L10(1.75,-2.25) L11(2.25,-2.25) L12(2.75,-2.25) M1(-2.75,-2.75) M2(-2.25,-2.75) M3(-1.75,-2.75) M4(-1.25,-2.75) M5(-0.75,-2.75) M6(-0.25,-2.75) M7(0.25,-2.75) M8(0.75,-2.75) M10(1.75,-2.75) M11(2.25,-2.75) M12(2.75,-2.75)
  silkscreen extent -3.87,-3.27 3.27,3.27, body extent -3.77,-3.77 3.77,3.77, height 0.25
AssemblyNote [mil] "Assembly Note"
AssemblyNoteLabel [mil] "Assembly Note for PCB Labels"
DRL0008A-MFG [mm]
  rrect33% 0.67x0.3 smd paste+0 mask+0: 1(-0.74,0.75) 2(-0.74,0.25) 3(-0.74,-0.25) 4(-0.74,-0.75) 5(0.74,-0.75) 6(0.74,-0.25) 7(0.74,0.25) 8(0.74,0.75)
  silkscreen extent -1.77,-1.28 0.65,1.28, body extent -0.8,-1.05 0.8,1.05, height 0.6
Fiducial10-20 [mm]
  round 1 smd mask+0.5: 1(0,0)
  Top Layer keep-out circle w1.178: c0,0 r0.5
FP-AC0402FR-0747K5L_0402-MFG [mm]
  rrect20% 0.5x0.6 smd paste+0 mask+0: 1(-0.5,0) 2(0.5,0)
  silkscreen extent -0.5,-0.67 0.5,0.67, body extent -0.5,-0.25 0.5,0.25, height 0.37
FP-CRCW040218K0FKEDC_0402-MFG [mm]
  rrect25% 0.4x0.6 smd paste+0 mask+0: 1(-0.45,0) 2(0.45,0)
  silkscreen extent -0.55,-0.67 0.55,0.67, body extent -0.5,-0.25 0.5,0.25, height 0.35
"FP-DFE201210U-R47M=P2_0805 (2012)-MFG" [mm]
  rrect13% 0.8x1.4 smd paste+0 mask+0: 1(-0.8,0) 2(0.8,0)
  silkscreen extent -1.2,-1.07 1.2,1.08, body extent -1,-0.6 1,0.6, height 1
FP-ERJ-1RHD1002C_0201-MFG [mm]
  rrect40% 0.25x0.3 smd paste+0 mask+0: 1(-0.3,0) 2(0.3,0)
  silkscreen extent -0.32,-0.54 0.32,0.54, body extent -0.3,-0.15 0.3,0.15, height 0.26
FP-ERJ-3GEY0R00V_0603-MFG [mm]
  rrect15% 0.65x0.9 smd paste+0 mask+0: 1(-0.725,0) 2(0.725,0)
  silkscreen extent -1.03,-0.87 1.03,0.87, body extent -0.8,-0.4 0.8,0.4, height 0.55
FP-FW4000044Q_4-SMD-2.0x1.6mm-MFG [mm]
  rrect13% 0.9x0.8 smd paste+0 mask+0: 1(-0.7,-0.55) 2(0.7,-0.55) 3(0.7,0.55) 4(-0.7,0.55)
  silkscreen extent -1.39,-1.35 1,1.35, body extent -1,-0.8 1,0.8, height 0.55
FP-GRM31CR70J226ME19K_1206-MFG [mm]
  rrect10% 1.05x1.6 smd paste+0 mask+0: 1(-1.475,0) 2(1.475,0)
  silkscreen extent -0.58,-0.9 0.58,0.9, body extent -1.6,-0.8 1.6,0.8, height 1.8
FP-GRM155R61A225ME01D_0402-MFG [mm]
  rrect25% 0.4x0.5 smd paste+0 mask+0: 1(-0.4,0) 2(0.4,0)
  silkscreen extent -0.5,-0.65 0.5,0.65, body extent -0.7,-0.38 0.7,0.38, height 0.25
FP-GRM188C71C475KE21D_0603-MFG [mm]
  rrect13% 0.75x0.9 smd paste+0 mask+0: 1(-0.775,0) 2(0.775,0)
  silkscreen extent -0.9,-0.9 0.9,0.9, body extent -0.8,-0.4 0.8,0.4, height 1
"FP-LQM2MPZR10MJHL_0806 (2016)-MFG" [mm]
  rrect13% 0.8x2.4 smd paste-1000 mask-1000: 1(-0.8,0) 2(0.8,0)
  silkscreen extent -1.1,-1.5 1.1,1.5, body extent -1,-0.8 1,0.8, height 1.2
"FP-RC0201JR-070RL_0201 (0603 Metric)-IPC_C" [mil]
  rrect38% 13.94x10.34 smd paste+0 mask+0: 1(-10.01,0) 2(10.01,0)
  body extent -12,-6 12,6, height 10
FP-RC0402JR-070RP_0402-MFG [mm]
  rrect20% 0.5x0.6 smd paste+0 mask+0: 1(-0.5,0) 2(0.5,0)
  silkscreen extent -0.5,-0.67 0.5,0.67, body extent -0.85,-0.4 0.85,0.4, height 0.25
FP-VLMY1500-GS08_0402-MFG [mm]
  rrect17% 0.6x0.7 smd paste+0 mask+0: 1(-0.475,0) 2(0.475,0)
  silkscreen extent -1.45,-0.72 0.6,0.72, body extent -0.87,-0.45 0.87,0.45, height 0.25
FP-W25Q16JVUXIQ_USON8-MFG [mm]
  rrect33% 0.6x0.3 smd paste-1000 mask-1000: 1(-1.25,0.75) 2(-1.25,0.25) 3(-1.25,-0.25) 4(-1.25,-0.75) 5(1.25,-0.75) 6(1.25,-0.25) 7(1.25,0.25) 8(1.25,0.75)
  rrect33% 0.3x1.7 smd paste-1000 mask+0: 9(0,0)
  silkscreen extent -2.32,-1.3 1.55,1.3, body extent -1.5,-1 1.5,1, height 0.6
SOT-323 [mm] "Diodes Inc recommended land pattern.  2016-02-24"
  rrect21% 0.6x0.47 smd: 1(-0.95,0.65) 2(-0.95,-0.65) 3(0.95,0)
  silkscreen extent -1.14,-1.22 0.78,1.22, body extent -1.13,-1.13 1.12,1.12, height 1.13
Sullins_GRPB122VWVN [mm] "Header, 1.27mm, 12x2, TH"
  rect 1x1 hole 0.7: 1(-0.635,6.985)
  round 1 hole 0.7: 2(0.635,6.985) 3(-0.635,5.715) 4(0.635,5.715) 5(-0.635,4.445) 6(0.635,4.445) 7(-0.635,3.175) 8(0.635,3.175) 9(-0.635,1.905) 10(0.635,1.905) 11(-0.635,0.635) 12(0.635,0.635) 13(-0.635,-0.635) 14(0.635,-0.635) 15(-0.635,-1.905) 16(0.635,-1.905) 17(-0.635,-3.175) 18(0.635,-3.175) 19(-0.635,-4.445) 20(0.635,-4.445) 21(-0.635,-5.715) 22(0.635,-5.715) 23(-0.635,-6.985) 24(0.635,-6.985)
  silkscreen extent -2,-7.62 1.7,7.62, body extent -1.7,-7.62 1.7,7.62, height 4
TI_Stacked_Overlay_Small [mil]
  silkscreen extent -418,-78 -237,98
TP_25MIL-SMT [mil]
  round 25 smd mask-2.5: 1(0,0)

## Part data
C2 C100: library part CMP-0006408-2, "CAP, CERM, 10 pF, 50 V, +/- 5%, C0G/NP0, 0402", Cap_Case=0402, Manufacturer=MuRata, Supplier Part Number 1=81-GRM1555C1H100JA1D, TempCo=C0G/NP0, Tolerance_%=5%, Value1=Unknown, Value2=50V, ValueDisplayed=10pF
C3 C78: library part CMP-0009692-3, "CAP, CERM, 1 uF, 6.3 V, +/- 20%, X5R, 0201", Cap_Case=0201, Manufacturer=MuRata, Supplier Part Number 1=490-7229-1-ND, TempCo=X5R, Tolerance_%=20%, Value1=Unknown, Value2=6.3V, ValueDisplayed=1uF
C4 C5 C7 C8 C10 C11 C12 C14 C16 C19 C21 C25 C26 C28 C29 C101: library part CMP-0006648-2, "CAP, CERM, 0.22 uF, 16 V, +/- 10%, X7R, 0402", Cap_Case=0402, Manufacturer=MuRata, Supplier Part Number 1=490-5418-1-ND, TempCo=X7R, Tolerance_%=10%, Value1=Unknown, Value2=16V, ValueDisplayed=0.22uF
C6: library part CMP-0006298-2, "CAP, CERM, 0.047 uF, 50 V, +/- 10%, X7R, 0402", Cap_Case=0402, Manufacturer=TDK, Supplier Part Number 1=445-7336-1-ND, TempCo=X7R, Tolerance_%=10%, Value1="0.06407 ohm", Value2=50V, ValueDisplayed=0.047uF
C9 C17 C20: library part CMP-0097887-1, "Chip Multilayer Ceramic Capacitors for General Purpose, 0402, 2.2uF, X5R, 15%, 20%, 10V", Manufacturer=Murata, Operating Temperature Range="-55¡ãC to +85¡ãC", TempCo=15%, Temperature Characteristic=X5R, Tolerance_%=20%, ValueDisplayed=2.2uF
C13 C15 C23 C44 C56 C62 C72 C119 C120 C128 C129: library part CMP-0007497-5, "CAP, CERM, 10 uF, 10 V, +/- 20%, X7R, 0603", Cap_Case=0603, Manufacturer=MuRata, Supplier Part Number 1=81-GRM188Z71A106MA3D, TempCo=X7R, Tolerance_%=20%, Value1=Unknown, Value2=10V, ValueDisplayed=10uF
C18 C22 C35: library part CMP-0064947-2, "CAP, CERM, 1 uF, 6.3 V,+/- 10%, X7R, 0402", Cap_Case=0402, Manufacturer=MuRata, Supplier Part Number 1=490-10024-1-ND, TempCo=X7R, Tolerance_%=10%, Value1=Unknown, Value2=6.3V, ValueDisplayed=1uF
C24 C27: library part CMP-0097886-1, "Chip Multilayer Ceramic Capacitors for General Purpose, 0603, 4.7uF, X7S, 22%, 10%, 16V", Manufacturer=Murata, Operating Temperature Range="-55¡ãC to +125¡ãC", TempCo=22%, Temperature Characteristic=X7S, Tolerance_%=10%, ValueDisplayed=4.7uF
C30 C45: library part CMP-0006658-2, "CAP, CERM, 0.01 uF, 25 V, +/- 10%, X7R, 0402", Cap_Case=0402, Manufacturer=MuRata, Supplier Part Number 1=490-1312-1-ND, TempCo=X7R, Tolerance_%=10%, Value1=Unknown, Value2=25V, ValueDisplayed=0.01uF
C31 C34 C53: library part CMP-0064969-1, "CAP, CERM, 0.1 uF, 10 V,+/- 10%, X7S, 0201", Cap_Case=0201, Manufacturer=MuRata, Supplier Part Number 1=490-14450-1-ND, TempCo=X7S, Tolerance_%=10%, Value1=Unknown, Value2=10V, ValueDisplayed=0.1uF
C32 C33: library part CMP-0006367-2, "CAP, CERM, 4.7 pF, 50 V, +/- 2%, C0G/NP0, 0402", Cap_Case=0402, Manufacturer=MuRata, Supplier Part Number 1=490-8102-1-ND, TempCo=C0G/NP0, Tolerance_%=2%, Value1=Unknown, Value2=50V, ValueDisplayed=4.7pF
C60 C66 C73: library part CMP-0007398-4, "CAP, CERM, 0.47 uF, 16 V, +/- 10%, X7R, 0603", Cap_Case=0603, Manufacturer=MuRata, Supplier Part Number 1=490-3295-1-ND, TempCo=X7R, Tolerance_%=10%, Value1=Unknown, Value2=16V, ValueDisplayed=0.47uF
C61 C79: library part CMP-0092150-1, "Chip Multilayer Ceramic Capacitors for General Purpose, 1206, 22uF, X7R, 15%, 20%, 6.3V", Manufacturer=Murata, Operating Temperature Range="-55¡ãC to +125¡ãC", TempCo=15%, Temperature Characteristic=X7R, Tolerance_%=20%, ValueDisplayed=22uF
C67 C69 C74: library part CMP-0006470-2, "CAP, CERM, 470 pF, 50 V, +/- 5%, C0G/NP0, 0402", Cap_Case=0402, Manufacturer=MuRata, Supplier Part Number 1=490-1297-1-ND, TempCo=C0G/NP0, Tolerance_%=5%, Value1=Unknown, Value2=50V, ValueDisplayed=470pF
C68: library part CMP-0008940-2, "CAP, CERM, 47 uF, 6.3 V, +/- 20%, X5R, 1206", Cap_Case=1206, Manufacturer=MuRata, Supplier Part Number 1=490-3907-1-ND, TempCo=X5R, Tolerance_%=20%, Value1="0.003 ohm", Value2=6.3V, ValueDisplayed=47uF
D3: library part CMP-0090807-1, "LED Uni-Color Yellow 588nm 2-Pin Chip 0402(1006Metric) T/R", Color=Yellow, Digikey Part Number=VLMY1500-GS08CT-ND, Forward Current=20mA, Manufacturer=Vishay, Mouser Part Number=78-VLMY1500-GS08, Operating Temperature Range="-30¡ãC to +85 ¡ãC", Power_TotalModule=75mW
FID1 FID2 FID3 FID4 FID5 FID6: library part CMP-0077181-1, "Fiducial mark.  There is nothing to buy or mount.", Manufacturer=N/A
J1: library part CMP-0054595-1, "Header, 1.27mm, 12x2, Gold, TH", Current_A=1A, Manufacturer="Sullins Connector Solutions", Supplier Part Number 1=S9015E-12-ND
L1 L5 L6: library part CMP-0095018-1, "100nH Shielded Multilayer Inductor 4A 19mOhm Max 0806 (2016 Metric)", Digikey Part Number=490-LQM2MPZR10MJHLCT-ND, Manufacturer=Murata, Mouser Part Number=81-LQM2MPZR10MJHL, Operating Temperature Range="-55¡ãC to +125¡ãC", Self Resonant Frequency=200MHz, Test Frequency=1MHz, Tolerance_%=20%
L2 L7: library part CMP-0077879-2, "Ferrite Bead, 120 ohm @ 100 MHz, 1.9 A, 0603", Manufacturer=MuRata, Supplier Part Number 1=490-13261-1-ND, Value1="0.04 ohm", Value2=1.9A, ValueDisplayed="120 ohm"
L14 L15: library part CMP-0092096-1, "470nH Shielded Wirewound Inductor 3A 42mOhm Max 0805 (2012 Metric)", Digikey Part Number=490-17727-1-ND, Manufacturer=Murata, Mouser Part Number=81-DFE201210U-R47MP2, Operating Temperature Range="-40¡ãC to +125¡ãC", Part Number=DFE201210U-R47M{}P2, Test Frequency=1MHz, Tolerance_%=20%
Logo1: library part CMP-0074838-1, "Texas Instrument Corporate Signature"
Q2: library part CMP-0000948-2, "MOSFET, N-CH, 100 V, 0.17 A, SOT-323", Alternate Manufacturer=None, Manufacturer="Diodes Inc.", Supplier Part Number 1=BSS123W-FDICT-ND, Value1=1
R1 R3 R5 R119: library part CMP-0093147-1, "Res Jumper Thick Film 0402 0 Ohm 5% 1/16W Molded SMD Paper T/R", Digikey Part Number=YAG1279CT-ND, Manufacturer=Yageo, Mouser Part Number=603-RC0402JR-070RP, Operating Temperature Range="-55¡ãC to +155¡ãC", Power_W=63mW
R2: library part CMP-0026367-2, "RES, 40.2 k, 1%, 0.063 W, AEC-Q200 Grade 0, 0402", Manufacturer=Vishay-Dale, Power_W=63mW, Supplier Part Number 1=541-40.2KLCT-ND, TempCo="100 ppm/C", Tolerance_%=1%, Value2=0.063W, Value_Code=40k2, ValueDisplayed=40.2k
R4 R44 R49 R73 R74 R75: library part CMP-0026245-2, "RES, 2.00 M, 1%, 0.063 W, AEC-Q200 Grade 0, 0402", Manufacturer=Vishay-Dale, Power_W=63mW, Supplier Part Number 1=541-2.00MLCT-ND, TempCo="100 ppm/C", Tolerance_%=1%, Value2=0.063W, Value_Code=2M00, ValueDisplayed=2.00M
R6 R7 R8: library part CMP-0089143-1, "0 Ohms Jumper 0.1W, 1/10W Chip Resistor 0603 (1608 Metric) Automotive AEC-Q200 Thick Film", Digikey Part Number=P0.0GCT-ND, Manufacturer=Panasonic, Mouser Part Number=667-ERJ-3GEY0R00V, Operating Temperature Range="-55¡ãC to +155¡ãC", Power_W=100mW, TempCo=-100/+600ppm/¡ãC, Tolerance_%=5%
R50: library part CMP-0095013-1, "Res Thick Film 0402 47.5K Ohm 1% 1/16W ¡À100ppm/¡ãC Molded SMD Paper T/R", Digikey Part Number=13-AC0402FR-0747K5LCT-ND, Manufacturer=Yageo, Mouser Part Number=603-AC0402FR-0747K5L, Operating Temperature Range="-55¡ãC to +155¡ãC", Power_W=62.5mW, TempCo=100ppm/¡ãC, Tolerance_%=1%
R67 R131 R165: library part CMP-0095015-1, "Res Thick Film 0201 10K Ohm 0.5% 0.05W ¡À50ppm/¡ãC Molded SMD Pressed Carrier T/R", Digikey Part Number=P15980CT-ND, Manufacturer=Panasonic, Mouser Part Number=667-ERJ-1RHD1002C, Operating Temperature Range="-55¡ãC to +125¡ãC", Power_W=50mW, TempCo=50ppm/¡ãC, Tolerance_%=0.5%
R86 R89: library part CMP-0027267-3, "RES, 1.00 k, 1%, 0.05 W, 0201", Manufacturer=Vishay-Dale, Power_W=50mW, Supplier Part Number 1=541-1.00KAABCT-ND, TempCo="100 ppm/C", Tolerance_%=1%, Value2=0.05W, Value_Code=1k00, ValueDisplayed=1.00k
R93: library part CMP-0027275-3, "RES, 33.2, 1%, 0.05 W, 0201", Manufacturer=Vishay-Dale, Power_W=50mW, Supplier Part Number 1=541-33.2ABCT-ND, TempCo="200 ppm/C", Tolerance_%=1%, Value2=0.05W, Value_Code=33R2, ValueDisplayed=33.2
R121: library part CMP-0078786-1, "RES, 68.1 k, 1%, 0.063 W, 0402", Manufacturer="Yageo America", Power_W=63mW, Supplier Part Number 1=YAG3213CT-ND, TempCo="100 ppm/C", Tolerance_%=1%, Value2=0.063W, Value_Code=68k1, ValueDisplayed=68.1k
R172 R179: library part CMP-0026704-1, "RES, 510, 1%, 0.1 W, 0402", Manufacturer=Panasonic, Power_W=100mW, Supplier Part Number 1=P510LCT-ND, TempCo="100 ppm/C", Tolerance_%=1%, Value2=0.1W, Value_Code=510R, ValueDisplayed=510
R175: library part CMP-0027261-3, "RES, 100 k, 1%, 0.05 W, 0201", Manufacturer=Vishay-Dale, Power_W=50mW, Supplier Part Number 1=541-100KAABCT-ND, TempCo="100 ppm/C", Tolerance_%=1%, Value2=0.05W, Value_Code=100k
R176: library part CMP-0086442-2, "RES SMD 0 OHM JUMPER 1/20W 0201", Manufacturer=Yageo, Power_W=50mW, TempCo=200ppm/¡ãC, Tolerance_%=5%
R178 R180: library part CMP-0094741-1, "Res Thick Film 0402 18K Ohm 1% 1/16W ¡À100ppm/¡ãC Molded SMD Paper T/R", Digikey Part Number=541-4757-1-ND, Manufacturer=Vishay, Mouser Part Number=71-CRCW040218K0FKEDC, Operating Temperature Range="-55¡ãC to +155¡ãC", Power_W=63mW, TempCo=100ppm/¡ãC, Tolerance_%=1%
R238 R244: library part CMP-0026727-1, "RES, 1.00 M, 1%, 0.063 W, 0402", Manufacturer="Yageo America", Power_W=63mW, Supplier Part Number 1=311-1.00MLRCT-ND, TempCo="100 ppm/C", Tolerance_%=1%, Value2=0.063W, Value_Code=1M00, ValueDisplayed=1.00M
TP5 TP9 TP11: library part CMP-0078143-4, "TEST POINT.  No entry in BOM.", Manufacturer=N/A
U1: library part CMP-0095272-2, Manufacturer="Texas Instruments", Operating Temperature Range=to
U2: library part CMP-0097318-1, "FLASH - NOR Memory IC 16Mb (2M x 8) SPI - Quad I/O 133 MHz 6 ns 8-USON (2x3)", Digikey Part Number=256-W25Q16JVUXIQTRCT-ND, Frequency_Fixed=532MHz, Manufacturer=Winbond, Max Supply Voltage=3.6V, Min Supply Voltage=2.7V, Mouser Part Number=454-W25Q16JVUXIQTR, Nominal Supply Current=2-20mA, Operating Temperature Range="-40¡ãC to +85¡ãC"
U19: library part CMP-0120067-1, "2.7-V to 6-V, 2-A Step-Down Converter in SOT583 Package", Manufacturer="Texas Instruments", Max Supply Voltage=6V, Min Supply Voltage=2.7V, Nominal Supply Current=17uA, Operating Temperature Range="-40¡ãC to +150¡ãC", Output Voltage=0.6-5.5V, Switching Frequency=1.8-4MHz
U20: library part CMP-0120069-1, "2.7-V to 6-V, 2-A Step-Down Converter in SOT583 Package", Manufacturer="Texas Instruments", Max Supply Voltage=6V, Min Supply Voltage=2.7V, Nominal Supply Current=17uA, Operating Temperature Range="-40¡ãC to +150¡ãC", Output Voltage=0.6-5.5V, Switching Frequency=1.8-4MHz
Y1: library part CMP-0090505-1, "40MHz ¡À10ppm Crystal 8pF 50 Ohms 4-SMD, No Lead", Digikey Part Number=FW4000044QDICT-ND, Frequency Stability=50ppm, Frequency Tolerance=10ppm, Frequency_Fixed=40MHz, Load Capacitance=8pF, Manufacturer=Diodes, Mouser Part Number=729-FW4000044Q, Operating Temperature Range="-40¡ãC to +125¡ãC"
ZZ1: library part CMP-0003616-3
ZZ2: library part CMP-0077236-1
ZZ3: library part CMP-0077237-1
ZZ4 ZZ5: library part CMP-0077238-1

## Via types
v1: diameter 18, hole 8, Top Layer to Bottom Layer, tented both sides, 1018 vias

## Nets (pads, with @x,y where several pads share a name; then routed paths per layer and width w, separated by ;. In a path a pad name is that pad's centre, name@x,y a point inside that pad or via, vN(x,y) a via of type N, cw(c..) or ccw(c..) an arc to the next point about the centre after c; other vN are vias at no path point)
COMP2: R178.1 U19.4 | length 71
  Bottom Layer w6: R178.1@221.61,217.05 225.82,221.26 238.04,221.26 266.56,249.78 266.56,258.12 U19.4@269.47,261.03
COMP3: R180.1 U20.4 | length 61.5
  Top Layer w6: U20.4@682.02,304.73 684.93,301.82 684.93,290.64 700.81,274.75 R180.1@724.59,274.75
DCA_LP_HOST_INTR_GPIO_0_LED: R3.2 R5.2 U1.J10 | length 1017.6
  Top Layer w4: v1(187.41,786.89) 187.81,787.28 207.28,787.28 U1.J10@207.67,787.68
  Top Layer w6: v1(503.87,204.31) 519.9,204.09 524.87,204.09 579.23,204.09 R5.2@583.21,204.03
  Bottom Layer w4: v1(187.41,786.89) 186.56,786.04 186.56,736.35 216.49,706.42 331.58,706.42 346.03,691.97 346.03,645.43
  Bottom Layer w6: 346.03,645.43 346.03,569.23 505.42,409.84 532.25,409.84 558.25,383.84 558.25,219.23 543.11,204.09 504.09,204.09 v1(503.87,204.31) 459.7,204.31 R3.2@454.31,198.92
DCA_LP_SPI_CLK_I2C_SCL: J1.20 R75.2 U1.D10 | length 1297.4
  Top Layer w6: v1(305.69,801.7) 305.9,801.49 305.9,787.88 U1.D10@306.1,787.68
  L3_PWR1 w6: J1.20@602.43,61.54 635.65,28.32 720.99,28.32 739.21,46.55 739.21,72.63 800.21,133.64 800.21,225.35 818.3,243.44 818.3,338.42 804.35,352.37 804.35,371.58 v1(802.56,373.37)
  Bottom Layer w4: v1(305.69,801.7) v1(305.69,801.7) 305.78,790.2 321.43,774.54 401.03,694.95 401.03,645.43
  Bottom Layer w6: 401.03,645.43 401.03,592.01 528.2,464.84 555.03,464.84 610.27,409.6 R75.2@795.2,409.6 ; J1.20@602.43,53.06 J1.20@602.43,61.54 ; R75.2@802.39,404.98 802.56,404.81 v1(802.56,373.37)
DCA_LP_SPI_CS_I2C_SDA: J1.17 R4.2 U1.D11 | length 916.3
  Top Layer w4: U1.D11@306.1,767.99 306.86,767.23 306.86,737.79 364.1,680.56 364.1,645.43
  Top Layer w6: 364.1,645.43 364.1,604.52 365.66,602.8 380.65,586.35 380.65,584.02 380.67,226.83 454.6,152.9 513.48,152.9 516.16,150.22 552.43,113.95 J1.17@552.43,111.54
  Bottom Layer w6: J1.17@552.43,111.54 558.81,117.93 558.81,130.36 617.09,188.64 627.24,188.64 R4.2@634.14,195.54
DCA_LP_SPI_MISO_REG_MODE: J1.19 U1.C11 | length 831.9
  Top Layer w4: U1.C11@325.79,767.99 314.86,757.07 314.86,743.79 337.13,721.52 337.21,721.52 375.1,683.63 375.1,645.43
  Top Layer w6: 375.1,645.43 375.1,609.59 391.67,591.34 391.67,589.02 391.67,233.2 460.72,164.14 549.83,164.14 J1.19@602.43,111.54
DCA_LP_SPI_MOSI: J1.21 U1.B12 | length 834.3
  Top Layer w4: U1.B12@345.47,747.74 399.37,693.83 399.37,645.43
  Top Layer w6: U1.B12@345.47,747.74 U1.B12@345.47,748.31 ; 399.37,645.43 399.37,618.7 416.46,601.62 416.46,242.31 472.46,186.31 580.3,186.31 592.6,186.3 617.54,161.36 v1(617.64,161.36)
  Bottom Layer w6: v1(617.64,161.36) 617.64,146.33 J1.21@652.43,111.54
